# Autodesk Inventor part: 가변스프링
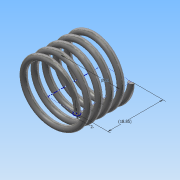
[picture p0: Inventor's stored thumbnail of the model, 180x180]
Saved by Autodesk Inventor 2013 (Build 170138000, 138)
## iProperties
Created: 2019-01
Part Number: 가변스프링
Material: 스테인리스강
Document SubType Name: Modeling
Designer: Administrator
Density: 8.08 g/cm^3
Mass: 7.77785 g
Surface Area: 19.6285 cm^2
Volume: 0.962606 cm^3
Author: Administrator
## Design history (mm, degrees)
sketch "스케치1"
  geometry: L1 (0, 0)-(10, 0); L2 (10, 0)-(10, 18.85); L3 (10, 18.85)-(0, 18.85); L4 (0, 18.85)-(0, 0); C1 r 1 at (10, 0)
  constraints: 8 end point, 2 parallel, 1 centre point, 1 coincident, 1 horizontal, 1 perpendicular
  dimensions: "d0" = 2 diameter of C1; "d1" = 20 diameter of L2 L4; "d2" = 18.85 distance between parallel lines of L1 L3 (derived)
feature "코일1" pitch "d3" = 10; turns "d5" = 5; dims "d4" = 18.85 (= d2), "d6" = 0, angle "d7" = 90 deg, angle "d8" = 90 deg, "d9" = 0, "d10" = 0
sketch "스케치2"
  geometry: L1 (-9, 0)-(-11, 0) reference; L2 (-9, 0)-(-11, 0) reference; 1 further point
  constraints: 2 horizontal alignment
extrude "돌출1" cut sketch "스케치2" stored distance "d11" = 10; taper "d12" = 0 deg
node "작업 평면1"
sketch "스케치3"
  geometry: L1 (9, 0)-(11, 0) reference; 1 further point
  constraints: 1 horizontal alignment
extrude "돌출2" cut sketch "스케치3" stored distance "d13" = 10; taper "d14" = 0 deg
node "솔리드1"
node "절단 모서리 투영1"
node "절단 모서리 투영2"
node "절단 모서리 투영3"
